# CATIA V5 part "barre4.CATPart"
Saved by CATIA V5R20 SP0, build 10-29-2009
Part number: barre4
Bounding box of the stored display mesh (mm): x -10 to 0, y -15.078 to 100.102, z 91.172 to 338.036
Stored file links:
  D:\Dropbox\IAO_2012\IAO_2012_748_omeyer\omeyer\omeyer\barre4.CATPart
  U:\Projet IAO\omeyer\Catia\Ass_748_skl.CATProduct
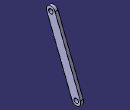
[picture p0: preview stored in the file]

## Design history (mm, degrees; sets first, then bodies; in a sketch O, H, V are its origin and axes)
Set1
  Plane1 "PlanRef": linked copy from another document
  DatumPoint1 "PointE": linked copy from another document
  DatumPoint2 "PointF": linked copy from another document
Body1 (main body)
  Sketch1 on Plane1, origin (0, 0, 0), H (0, 1, 0), V (0, 0, 1)
    construction line L1 (-0.0869, 323.0365) -> (85.1115, 106.172)
    point P1 (-0.0869, 323.0365)
    point P2 (85.1115, 106.172)
    line L2 (13.8744, 328.5214) -> (99.0727, 111.6568)
    line L3 (71.1503, 100.6871) -> (-14.0481, 317.5517)
    arc A1 centre (85.1115, 106.172) radius 15 from (99.0727, 111.6568) to (71.1503, 100.6871) cw
    arc A2 centre (-0.0869, 323.0365) radius 15 from (-14.0481, 317.5517) to (13.8744, 328.5214) cw
    reference projected point E1 (-0.0869, 323.0365) from DatumPoint1
    reference projected point E2 (85.1115, 106.172) from DatumPoint2
    circle A3 centre (85.1115, 106.172) radius 7.5
    point P7 (85.1115, 106.172)
    circle A4 centre (-0.0869, 323.0365) radius 7.5
    point P8 (-0.0869, 323.0365)
    reference projected point E3 (-0.0869, 323.0365) from DatumPoint1
    reference projected point E4 (85.1115, 106.172) from DatumPoint2
    distance L1 L2 = 15
    radius A4 = 7.5
    radius A3 = 7.5
    tangency: A1 L2, A2 L2, A1 L3, A2 L3
    coincidence: P1 E1, P2 E2, P8 E3, P7 E4
  Pad1: profile Sketch1, direction (-1, 0, 0), length 10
